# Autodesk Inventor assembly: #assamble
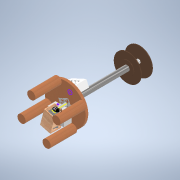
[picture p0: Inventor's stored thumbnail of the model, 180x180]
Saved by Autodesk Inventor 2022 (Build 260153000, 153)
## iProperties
Created: 2021-07
Part Number: #assamble
Document SubType Name: Assembly
Designer: ASUS
Author: ASUS
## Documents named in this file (10)
- C:\Users\ASUS\Downloads\#assamble.iam
- C:\Users\ASUS\Downloads\outer rod.ipt
- C:\Users\ASUS\Downloads\table.ipt
- C:\Users\ASUS\Downloads\inner rod.ipt
- C:\Users\ASUS\Downloads\cymbal.ipt
- C:\Users\ASUS\Downloads\cymbal2.ipt
- C:\Users\ASUS\Downloads\table top.ipt
- C:\Users\ASUS\Downloads\dj.iam
- C:\Users\ASUS\Downloads\control board.ipt
- C:\Users\ASUS\Downloads\dabbi.ipt
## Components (9 placed, 9 different names)
1. outer rod:1 — Rigid:1, Cylindrical:1, Rigid:2, Rigid:4
2. table:1 — Rigid:1, Mate:1
3. inner rod:1 — Cylindrical:1, Rigid:3, Planar:1
4. cymbal:1 — Rigid:2
5. cymbal2:1 — Rigid:3
6. table top:1 — Rigid:4, Rigid:5
7. dj:1 [sub-assembly] — Planar:1
8. control board:1 — Rigid:5
9. dabbi:1 — Mate:1
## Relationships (8: WeldJoint 5, CylindricalJoint 1, PlanarJoint 1, Mate 1)
- Rigid:1 [WeldJoint]: outer rod:1 ↔ table:1
- Cylindrical:1: outer rod:1 ↔ inner rod:1
- Rigid:2 [WeldJoint]: outer rod:1 ↔ cymbal:1
- Rigid:3 [WeldJoint]: inner rod:1 ↔ cymbal2:1
- Rigid:4 [WeldJoint]: outer rod:1 ↔ table top:1
- Planar:1: inner rod:1 ↔ dj:1
- Rigid:5 [WeldJoint]: table top:1 ↔ control board:1
- Mate:1: table:1 ↔ dabbi:1
